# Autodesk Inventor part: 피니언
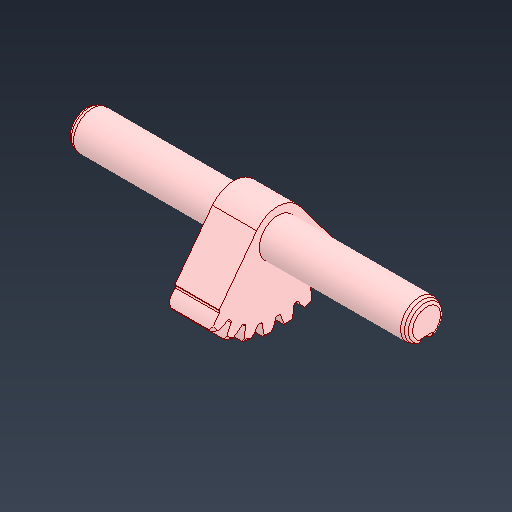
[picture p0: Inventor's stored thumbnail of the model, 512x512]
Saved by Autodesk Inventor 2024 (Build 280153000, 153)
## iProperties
Created: 2024-05
Part Number: 피니언
Material: 강철, 탄소
Document SubType Name: Modeling
Designer: kh_501
Density: 7.85 g/cm^3
Appearance: 기본값
Author: jhkim
Sending System: Autodesk Inventor 2025
Preprocessor: ST-DEVELOPER v20
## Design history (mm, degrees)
node "피니언1"
node "솔리드2"
node "솔리드1"
